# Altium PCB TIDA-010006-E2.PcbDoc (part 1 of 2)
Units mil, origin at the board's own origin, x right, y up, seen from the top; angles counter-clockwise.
Board outline 2251.83 x 2520.68 mil, 2 copper layers (Top Layer, Bottom Layer), stack 62 mil thick; 89 components, 37 nets, 190 pads, 37 vias.
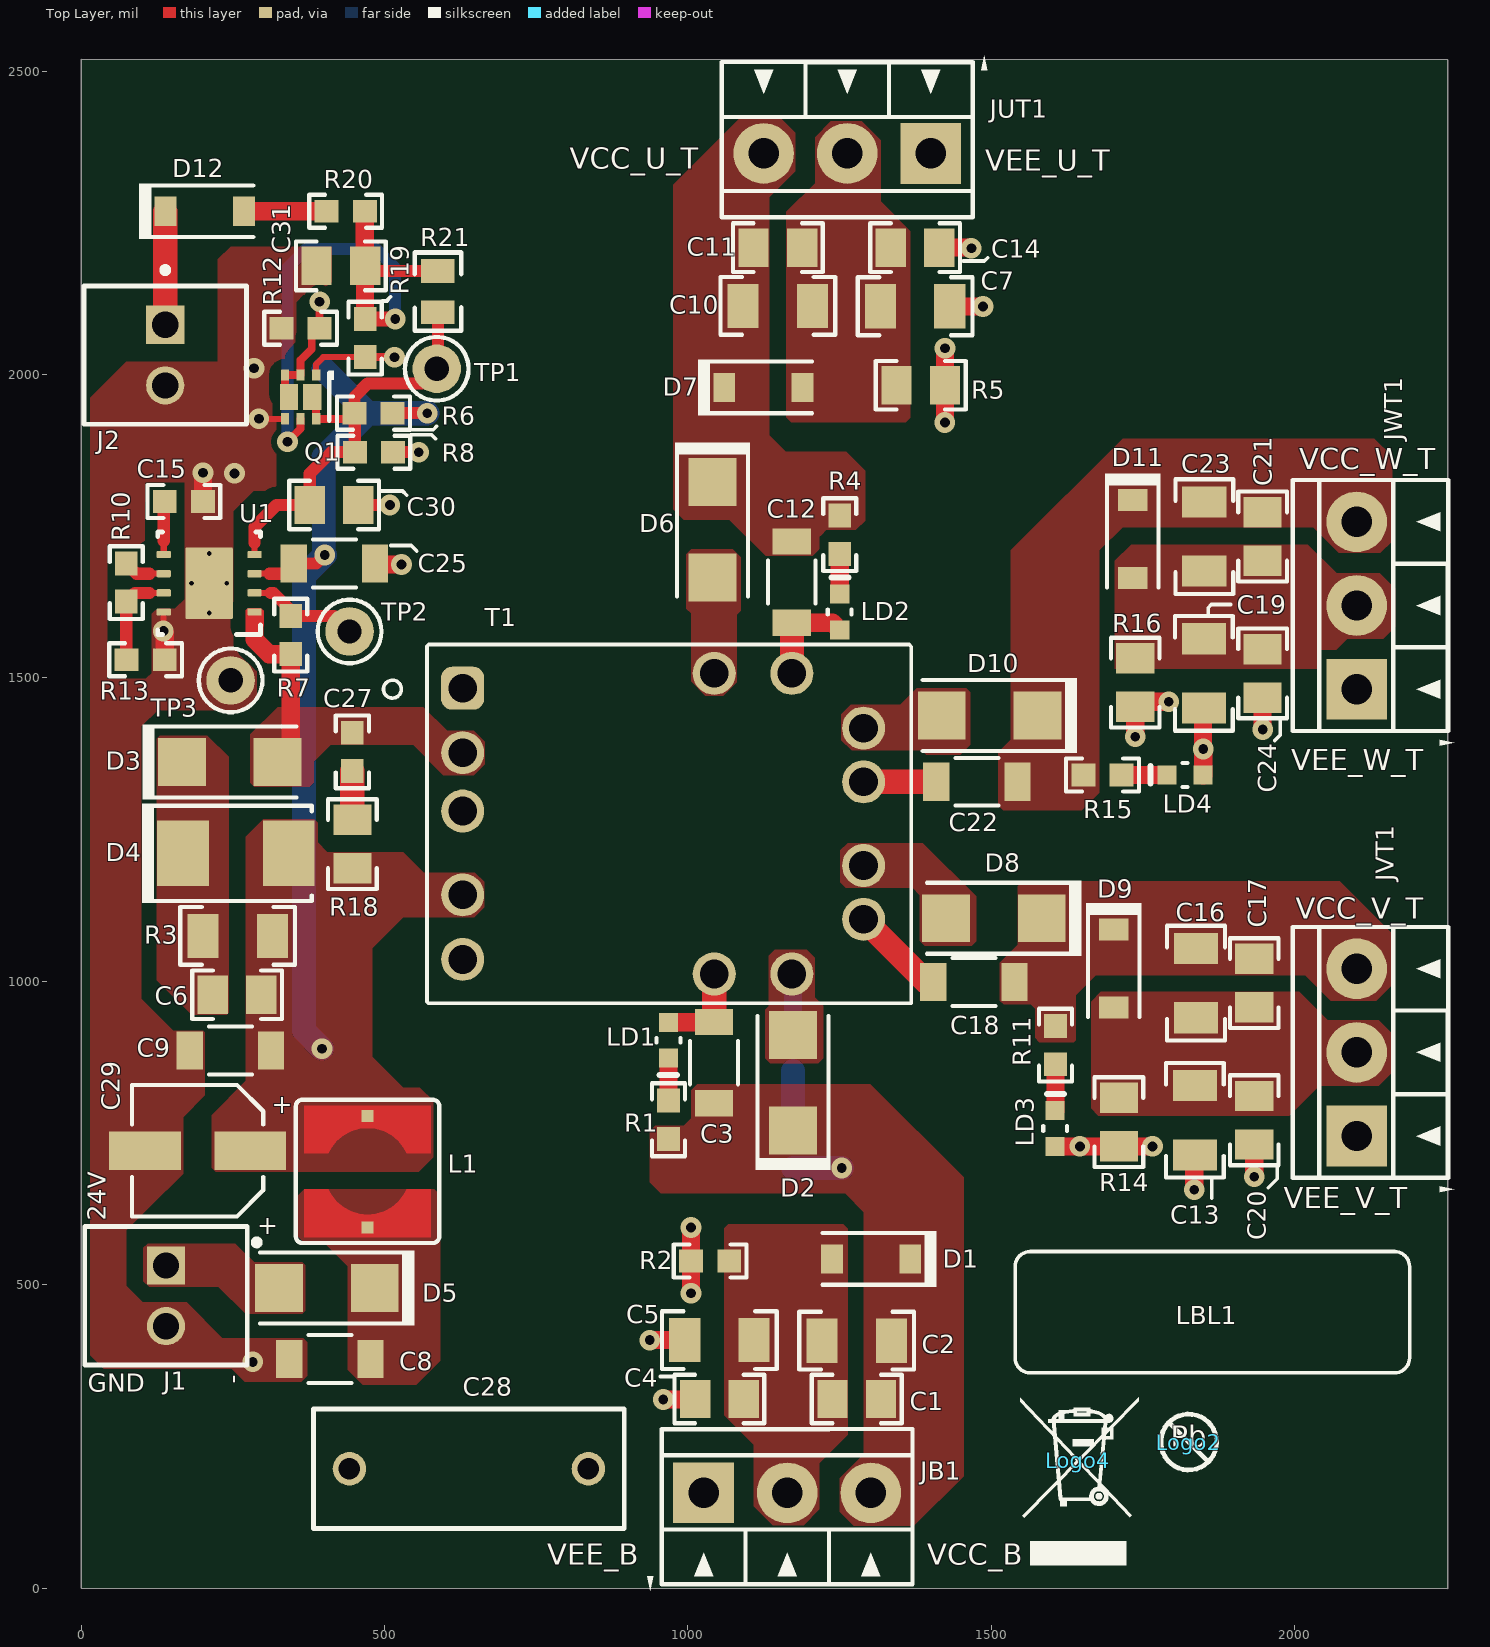
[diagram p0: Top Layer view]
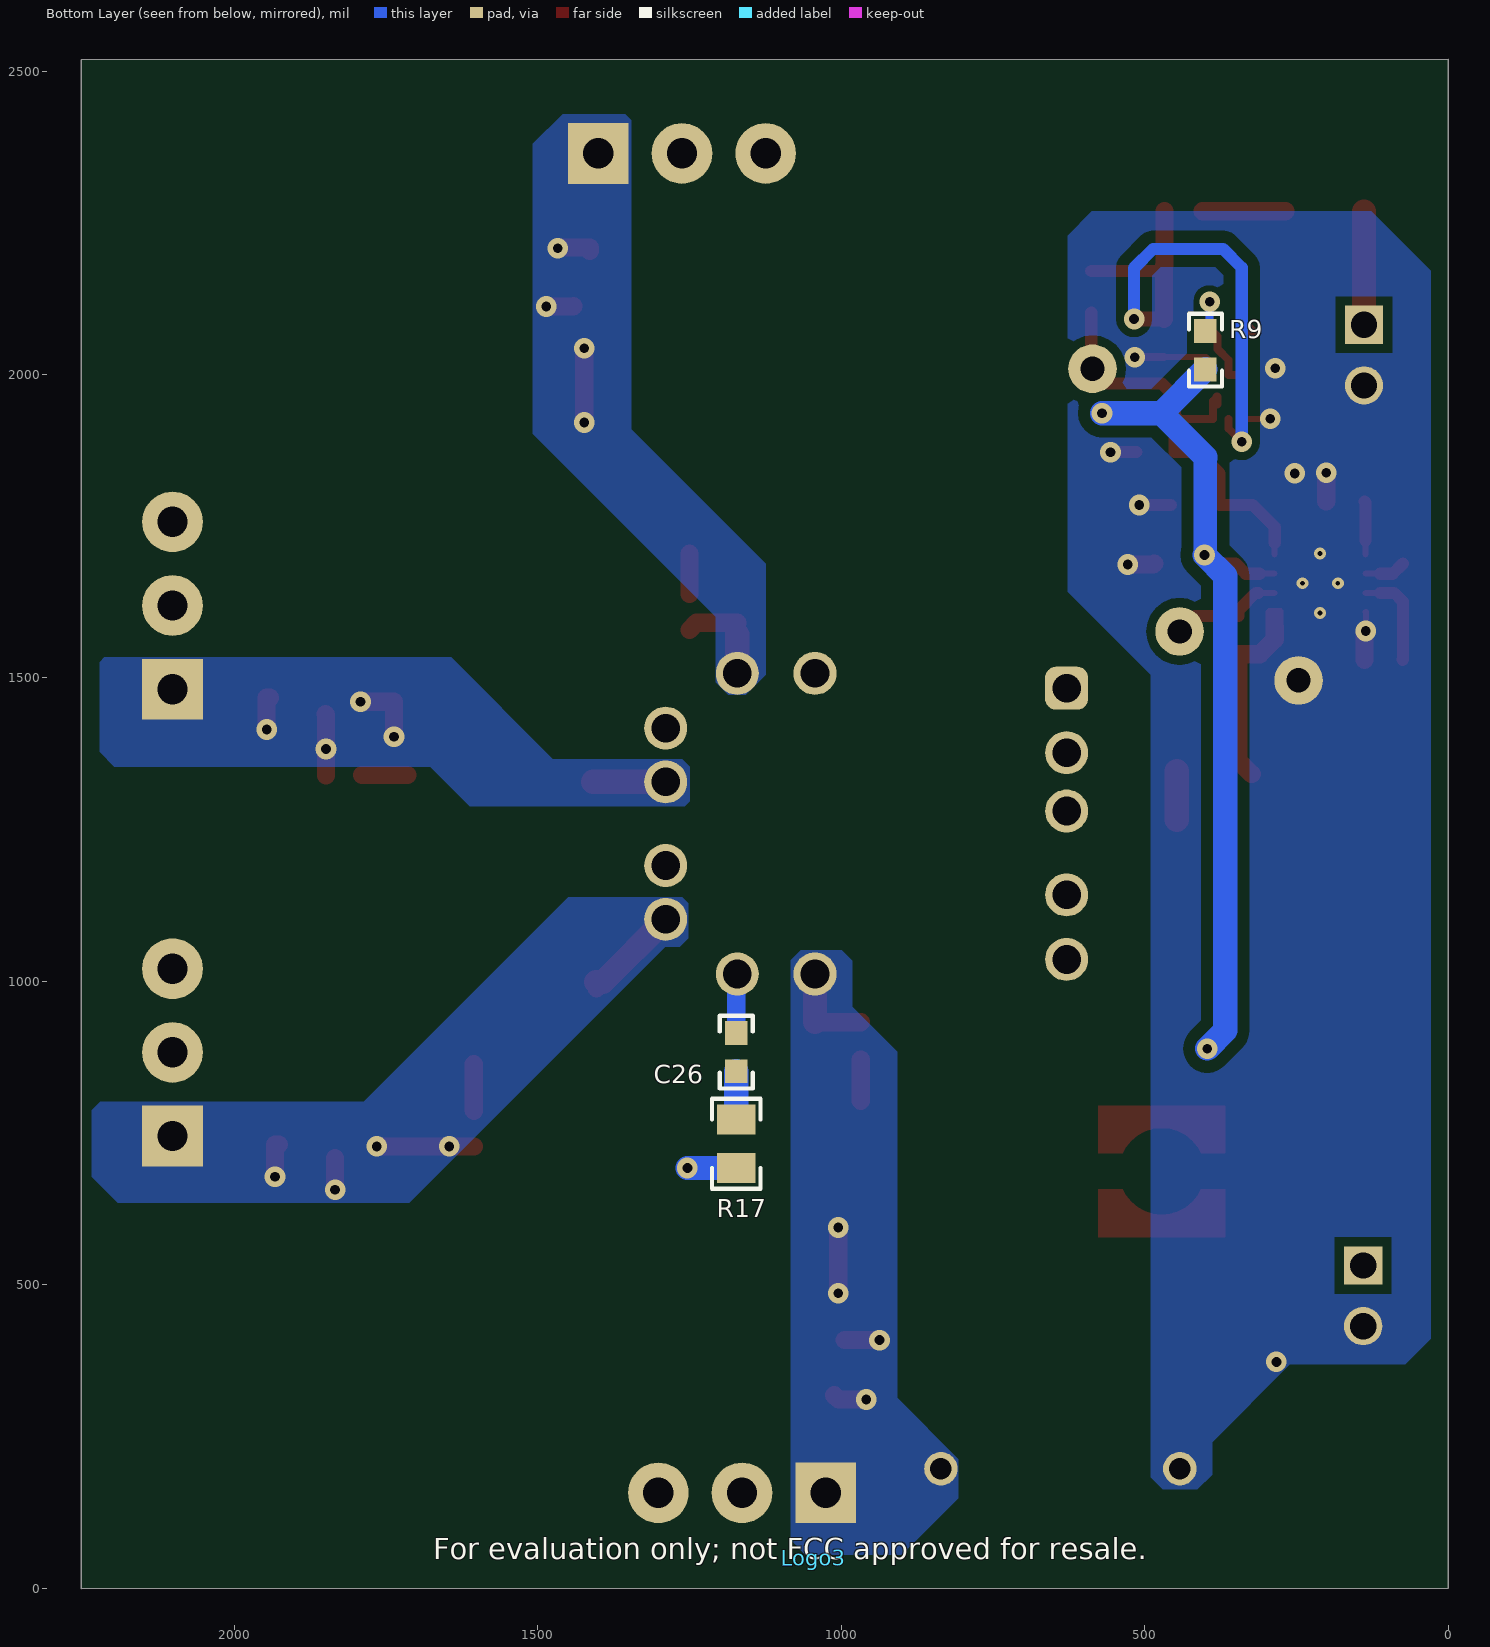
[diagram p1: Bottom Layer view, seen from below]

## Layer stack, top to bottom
Top Solder: solder mask 0.4, Solder Resist, Dk 3.5
Top Layer: signal copper 1.4
Dielectric1: core 59.2, FR-4 High Tg, Dk 4.8
Bottom Layer: signal copper 1.4
Bottom Solder: solder mask 0.4, Solder Resist, Dk 3.5

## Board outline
0,0 0,2519.68 2251.83,2518.68 2251.83,-1

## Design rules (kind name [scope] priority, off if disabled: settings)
AcuteAngle [All] p1: minimum=4.50000000000000E+0001 checktracksonly=FALSE
AssemblyTestPointUsage [All] p1: valid=2
BoardOutlineClearance BoardOutlineClearance_MountingHoles [OnCopper and InComponentClass('Mounting Holes')] p1: gap=20 ignorepadtopadclearanceinfootprint=FALSE
BoardOutlineClearance BoardOutlineClearance_Poly [OnCopper and IsPoly] p2: gap=15 ignorepadtopadclearanceinfootprint=FALSE
BoardOutlineClearance [OnCopper and Not InComponentClass('Logo') and not InComponentClass('FiducialMark') and not InRegion(1000,500,4000,800) and not InPoly] p3: gap=20 ignorepadtopadclearanceinfootprint=FALSE
Clearance Clearance_Keepouts [((IsTrack Or IsArc) And Not InPoly) And IsFree and IsKeepOut vs ((IsTrack Or IsArc) And Not InPoly) And IsFree and IsKeepOut] p1: gap=0 ignorepadtopadclearanceinfootprint=FALSE
Clearance Clearance_Poly [InPolygon] p2: gap=25 ignorepadtopadclearanceinfootprint=FALSE except(0: Arc-Hole Track-Hole SMDPad-Hole THPad-Hole Via-Hole Fill-Hole Poly-Hole Region-Hole Text-Hole; 10: Via-Fill Via-Poly Via-Region; 12: SMDPad-Fill SMDPad-Poly SMDPad-Region; 15: THPad-Fill THPad-Poly THPad-Region; 20: Arc-Fill Arc-Poly Arc-Region Track-Fill Track-Poly Track-Region)
Clearance Clearance_FiducialMark [IsKeepOut and InComponentClass('FiducialMark') vs IsPad and InComponentClass('FiducialMark')] p3: gap=0 ignorepadtopadclearanceinfootprint=FALSE
Clearance [All] p4: gap=7.87 ignorepadtopadclearanceinfootprint=TRUE except(0: Arc-Hole Track-Hole SMDPad-Hole THPad-Hole Via-Hole Fill-Hole Poly-Hole Region-Hole Text-Hole)
ComponentClearance ComponentClearance_MountingHoles_FiducialMarks [InComponentClass('Mounting Holes') vs InComponentClass('FiducialMark')] p1: gap=50 collisioncheckmode=3 verticalgap=10 showdistances=FALSE
ComponentClearance ComponentClearance_Shunt [InComponentClass('Header') vs InComponentClass('Shunt')] p2: gap=0 collisioncheckmode=3 verticalgap=0 showdistances=FALSE
ComponentClearance ComponentClearance_Logo [InComponentClass('Logo')] p3: gap=10 collisioncheckmode=3 verticalgap=10 showdistances=FALSE
ComponentClearance ComponentClearance_ScrewToNut [(HasFootprint('NY PMS 440 0025 PH')) vs (HasFootprint('Keystone_1902C'))] p4: gap=5 collisioncheckmode=3 verticalgap=10 showdistances=FALSE
ComponentClearance ComponentClearance_MountingHoles [InComponentClass('Mounting Holes')] p5: gap=15 collisioncheckmode=3 verticalgap=100000 showdistances=FALSE
ComponentClearance ComponentClearance_SmallPassives [HasFootprint('0201*') or HasFootprint('0402*') or HasFootprint('0508') or HasFootprint('0603*') or HasFootprint('0612') or HasFootprint('0805*') or HasFootprint('0815*') or HasFootprint('0830*') or HasFootprint('1206*') or HasFootprint('1210*') or HasFootprint('1808*') or HasFootprint('1812*') or HasFootprint('1825*') or HasFootprint('2010*') or HasFootprint('2220*') or HasFootprint('2225*') or HasFootprint('2512*') or HasFootprint('2728*') or HasFootprint('3518*') vs HasFootprint('0201*') or HasFootprint('0402*') or HasFootprint('0508') or HasFootprint('0603*') or HasFootprint('0612') or HasFootprint('0805*') or HasFootprint('0815*') or HasFootprint('0830*') or HasFootprint('1206*') or HasFootprint('1210*') or HasFootprint('1808*') or HasFootprint('1812*') or HasFootprint('1825*') or HasFootprint('2010*') or HasFootprint('2220*') or HasFootprint('2225*') or HasFootprint('2512*') or HasFootprint('2728*') or HasFootprint('3518*')] p6: gap=14.96 collisioncheckmode=3 verticalgap=10 showdistances=FALSE
ComponentClearance ComponentClearance_THtoSMT [IsThruComponent vs IsSMTComponent] p7: gap=15 collisioncheckmode=3 verticalgap=30 showdistances=FALSE
ComponentClearance ComponentClearance_THtoTH [IsThruComponent vs IsThruComponent] p8: gap=15 collisioncheckmode=3 verticalgap=30 showdistances=FALSE
ComponentClearance [All] p9: gap=15 collisioncheckmode=3 verticalgap=10 showdistances=FALSE
DiffPairsRouting [All] p1: maxlimit=100 minlimit=10 mostfreqgap=10 toplayer_minwidth=15 toplayer_maxwidth=15 toplayer_prefwidth=15 bottomlayer_minwidth=15 bottomlayer_maxwidth=15 bottomlayer_prefwidth=15 maxuncoupledlength=1000
FabricationTestPointUsage TestPointUsage [All] p1: valid=2 allowmultiple=FALSE
FabricationTestpoint Testpoint [All] p1: side=3 testpointundercomponent=TRUE minsize=40 maxsize=100 preferedsize=60 minholesize=0 maxholesize=40 preferedholesize=32 testpointgrid=1 allowsidetop=TRUE allowsidebottom=TRUE usegrid=TRUE gridtolerance=0.01
FanoutControl Fanout_LCC [IsLCC] p1: bgadir=Out bgaviamode=Centered fanoutstyle=Auto fanoutdirection=Alternating viagrid=1 // Fanout_LCC (Default Rule)
FanoutControl Fanout_BGA [IsBGA] p2: bgadir=Out bgaviamode=Centered fanoutstyle=Auto fanoutdirection=Alternating viagrid=1 // Fanout_BGA (Default Rule)
FanoutControl Fanout_Default [All] p4: bgadir=Out bgaviamode=Centered fanoutstyle=Auto fanoutdirection=Alternating viagrid=1 // Fanout_Default (Default Rule)
FanoutControl Fanout_Small [(CompPinCount < 5)] p5: bgadir=Out bgaviamode=Centered fanoutstyle=Auto fanoutdirection=OutThenIn viagrid=1 // Fanout_Small (Default Rule)
HoleSize [All] p1: absolutevalues=TRUE maxlimit=251 minlimit=7.87 maxpercent=80.000 minpercent=20.000
MinimumAnnularRing MinimumAnnularRing_ThermalPadVias [IsVia and InAnyComponent] p1: minimumring=5.91
MinimumAnnularRing [All] p2: minimumring=8
MinimumSolderMaskSliver MinimumSolderMaskSliver_Logo [InComponentClass('Logo') vs InComponentClass('Logo')] p1: minsoldermaskwidth=0.7
MinimumSolderMaskSliver [All] p2: minsoldermaskwidth=3.94
PlaneConnect [All] p1: planeconnectstyle=Relief reliefexpansion=10 reliefentries=4 reliefconductorwidth=10 reliefairgap=10
PolygonConnect [All] p1: connectstyle=Direct reliefconductorwidth=10 reliefentries=4 polygonreliefangle="90 Angle" airgapwidth=10
RoutingVias ThermalPadVias [IsVia and InAnyComponent] p1: holewidth=7.87 width=19.68 viastyle="Through Hole" minholewidth=7.87 minwidth=19.68 maxholewidth=12.99 maxwidth=23.62
RoutingVias [All] p2: holewidth=16 width=34 viastyle="Through Hole" minholewidth=7.87 minwidth=26 maxholewidth=40 maxwidth=65
SilkToBoardRegionClearance [Not ((IsComment or IsDesignator) And (Hide <> 'False')) and not InRegion(1000,500,4000,800)] p1:
SilkToSilkClearance SilkToSilkClearance_Pb-FreeLogo [(HasFootprint('Pb-Free_Overlay_Medium') OR HasFootprint('Pb-Free_Overlay_Small')) vs (HasFootprint('Pb-Free_Overlay_Medium') OR HasFootprint('Pb-Free_Overlay_Small'))] p1: silktosilkclearance=0
SilkToSilkClearance [All] p2: silktosilkclearance=4
SilkToSolderMaskClearance SilkToComponentPadClearance [(IsPad or IsFill or IsRegion) and InAnycomponent] p1: minsilkscreentomaskgap=5 clearancetoexposedcopper=TRUE
SilkToSolderMaskClearance "Silk to Solder Mask Opening" [All] p2: minsilkscreentomaskgap=4 clearancetoexposedcopper=FALSE
SolderMaskExpansion [All] p1: expansion=1.97
Width [All] p1: maxlimit=100 minlimit=6 preferedwidth=10 checkconnectedcopper=TRUE
15 further rules are at their usual default settings.

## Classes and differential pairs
component class Label: LBL1
component class AssemblyNote: ZZ1 ZZ2 ZZ3 ZZ4
component class TIDA010006_EVM_Hardware: LBL1 Logo2 Logo3 Logo4 ZZ1 ZZ2 ZZ3 ZZ4
component class TIDA010006Refresh_BlankSheet: C1 C2 C3 C4 C5 C6 C7 C8 C9 C10 C11 C12 C13 C14 C15 C16 C17 C18 C19 C20 C21 C22 C23 C24 C25 C26 C27 C28 C29 C30 C31 D1 D2 D3 D4 D5 D6 D7 D8 D9 D10 D11 D12 J1 J2 JB1 JUT1 JVT1 JWT1 L1 LD1 LD2 LD3 LD4 Q1 R1 R2 R3 R4 R5 R6 R7 R8 R9 R10 R11 R12 R13 R14 R15 R16 R17 R18 R19 R20 R21 T1 TP1 TP2 TP3 U1

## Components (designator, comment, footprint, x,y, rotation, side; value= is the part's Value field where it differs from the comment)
C1 "UMK212B7104KG-T" 0805_HV 1278,312 r180 top value=0.1uF
C2 "GMK316AB7106KL" 1206 1278,408 r180 top value=10uF
C3 "C3216X7R1H475K160AC" 1206_180 1043,866 r90 top value=4.7uF
C4 "UMK212B7104KG-T" 0805_HV 1051.7,312 r180 top value=0.1uF
C5 "EMK316BB7226ML-T" 1206 1051.7,409.06 r180 top value=22uF
C6 "C0805C124K1RACTU" 0805_HV 257,978 r0 top value=0.12uF
C7 "EMK316BB7226ML-T" 1206 1374.22,2112.46 r0 top value=22uF
C8 "C3216X7R1H475K160AC" 1206_180 410,378 r180 top value=4.7uF
C9 "C3216X7R1H475K160AC" 1206_180 246,886 r180 top value=4.7uF
C10 "GMK316AB7106KL" 1206 1148,2113 r0 top value=10uF
C11 "UMK212B7104KG-T" 0805_HV 1148,2209 r0 top value=0.1uF
C12 "C3216X7R1H475K160AC" 1206_180 1171,1658 r270 top value=4.7uF
C13 "EMK316BB7226ML-T" 1206 1835.2,771.2 r270 top value=22uF
C14 "UMK212B7104KG-T" 0805_HV 1374.22,2209 r0 top value=0.1uF
C15 "GRM188R71H392KA01D" 0603 169.43,1790.63 r0 top value=3900pF
C16 "GMK316AB7106KL" 1206 1837,997.17 r270 top value=10uF
C17 "UMK212B7104KG-T" 0805_HV 1933,997.17 r270 top value=0.1uF
C18 "C3216X7R1H475K160AC" 1206_180 1471,999 r180 top value=4.7uF
C19 "EMK316BB7226ML-T" 1206 1850,1507.53 r270 top value=22uF
C20 "UMK212B7104KG-T" 0805_HV 1933,771.2 r270 top value=0.1uF
C21 "UMK212B7104KG-T" 0805_HV 1946.8,1733 r270 top value=0.1uF
C22 "C3216X7R1H475K160AC" 1206_180 1476,1329 r180 top value=4.7uF
C23 "GMK316AB7106KL" 1206 1850.8,1733 r270 top value=10uF
C24 "UMK212B7104KG-T" 0805_HV 1946.8,1507.53 r270 top value=0.1uF
C25 "C3216X7R1H475K160AC" 1206_180 417.43,1688.63 r0 top value=4.7uF
C26 "GRM188R72A221KA01D" 0603 1173,883.5 r270 bottom value=220pF
C27 "GRM188R72A221KA01D" 0603 447,1378.26 r270 top value=220pF
C28 "890334023006" WCAP-FTXX_P10PL20_13x5x11 639,197 r180 top value=0.01uF
C29 "EMVA500ADA100ME55G" CAPSMT_62_E55 192,721 r180 top value=10uF
C30 "0805YC334KAT2A" 0805_HV 416.83,1785 r0 top value=0.33uF
C31 "UMK212B7104KG-T" 0805_HV 428,2179 r180 top value=0.1uF
D1 "MMSZ4702T1G" SOD-123 1301.7,542.74 r180 top value=15V
D2 "B2100A-13-F" SMA 1173,833 r90 top value=100V
D3 "B2100A-13-F" SMA 245,1361.63 r0 top value=100V
D4 "1SMB5942BT3G" SMB 255,1211 r0 top value=51V
D5 "B2100A-13-F" SMA 405,495 r180 top value=100V
D6 "B2100A-13-F" SMA 1040.43,1744.26 r270 top value=100V
D7 "MMSZ4702T1G" SOD-123 1124.22,1978.78 r0 top value=15V
D8 "B2100A-13-F" SMA 1504,1104 r180 top value=100V
D9 "MMSZ4702T1G" SOD-123 1701.52,1021.2 r270 top value=15V
D10 "B2100A-13-F" SMA 1497,1438 r180 top value=100V
D11 "MMSZ4702T1G" SOD-123 1732.8,1729 r270 top value=15V
D12 "MMSZ5248B-7-F" SOD-123 203.73,2269 r0 top value=18V
J1 "282834-2" TEC_282834-2 140,482 r270 top
J2 "282834-2" TEC_282834-2 138.63,2032 r270 top
JB1 "ED555/3DS" TERM_BLK_ED555-3DS 1025.7,157.26 r0 top
JUT1 "ED555/3DS" TERM_BLK_ED555-3DS 1400.22,2364.26 r180 top
JVT1 "ED555/3DS" TERM_BLK_ED555-3DS 2101.8,745.2 r90 top
JWT1 "ED555/3DS" TERM_BLK_ED555-3DS 2101.8,1481.53 r90 top
L1 "744042100" WE-TPC-M1 472,687 r90 top value=10uH
LBL1 "THT-14-423-10" Label_650x200 1864,455 r0 top
LD1 "LED_LG L29K-G2J1-24-Z" "LG L29K_GREEN" 968,903 r270 top value=Green
LD2 "LED_LG L29K-G2J1-24-Z" "LG L29K_GREEN" 1250,1608.76 r90 top value=Green
LD3 "LED_LG L29K-G2J1-24-Z" "LG L29K_GREEN" 1605,757.5 r90 top value=Green
LD4 "LED_LG L29K-G2J1-24-Z" "LG L29K_GREEN" 1819,1340 r180 top value=Green
Logo2 "Pb-Free Symbol" Pb-Free_Overlay_Small 1825,241 r0 top
Logo3 "FCC disclaimer" FCC_disclaimer 1045,50 r180 bottom
Logo4 "WEEE logo" WEEE_Minimum 1643,210 r0 top
Q1 "NSS60101DMTTBG" DFN2x2MM_6L 361.63,1963 r270 top value="60 V"
R1 "RC0603FR-0718KL" 0603 968,772 r270 top value=18.0k
R2 "RC0603FR-079K1L" 0603 1036.43,539.26 r0 top value=9.10k
R3 "ERJ-8ENF3481V" 1206 258,1075 r180 top value=3.48k
R4 "RC0603FR-0718KL" 0603 1250,1736 r90 top value=18.0k
R5 "RC0805FR-07649RL" 0805_HV 1383.49,1982.26 r180 top value=649
R6 "RT0603BRD07261KL" 0603 481.83,1936.28 r0 top value=261k
R7 "RC0603FR-07210KL" 0603 345.43,1570.63 r270 top value=210k
R8 "RC0603FR-0720KL" 0603 482.5,1872 r180 top value=20.0k
R9 "RT0603BRD07261KL" 0603 400,2040 r270 bottom value=261k
R10 "RC0603FR-07665KL" 0603 74.43,1657.17 r90 top value=665k
R11 "RC0603FR-0718KL" 0603 1605.46,895 r90 top value=18.0k
R12 "RC0603FR-0720KL" 0603 361.63,2076 r0 top value=20.0k
R13 "RT0603DRE0712K1L" 0603 106.43,1530 r180 top value=12.1k
R14 "RC0805FR-07649RL" 0805_HV 1710,768.11 r90 top value=649
R15 "RC0603FR-0718KL" 0603 1683,1340 r180 top value=18.0k
R16 "RC0805FR-07649RL" 0805_HV 1736.8,1492.26 r90 top value=649
R17 "RG2012P-101-B-T5" 0805_HV 1173,732.5 r90 bottom value=100
R18 "RG2012P-101-B-T5" 0805_HV 447,1226.26 r90 top value=100
R19 "RC0603FR-0720KL" 0603 468,2060 r270 top value=20.0k
R20 "RG1608P-2211-B-T5" 0603 436,2269 r180 top value=2.21k
R21 "5106" 5106 588,2137 r270 top value=0
T1 "750343953" Wurth_EPW15_5996 959,1259.84 r0 top locked value=47uH
TP1 "5000" Keystone5000 586,2009.46 r90 top
TP2 "5000" Keystone5000 442.43,1576.63 r90 top
TP3 "5001" Keystone5001 246.43,1496 r90 top
U1 "LM5180QNGURQ1" NGU0008C 211,1656 r180 top
ZZ1 "This Assembly Note is for PCB labels only" AssemblyNoteLabel -943.43,3340.63 r0 top
ZZ2 "These assemblies are ESD sensitive, ESD precautions shall be observed." AssemblyNote -943.43,3231.74 r0 top
ZZ3 "These assemblies must be clean and free from flux and all contaminants. Use of no clean flux is not acceptable." AssemblyNote -943.43,3143.19 r0 top
ZZ4 "These assemblies must comply with workmanship standards IPC-A-610 Class 2, unless otherwise specified." AssemblyNote -943.43,3054.63 r0 top

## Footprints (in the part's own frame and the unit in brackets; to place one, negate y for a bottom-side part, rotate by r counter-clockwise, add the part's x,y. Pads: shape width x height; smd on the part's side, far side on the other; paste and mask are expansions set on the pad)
0603 [mm] "0603 from SM-752 data"
  rect 1x0.95 smd: 1(-0.8,0) 2(0.8,0)
  silkscreen extent -1.52,-0.69 1.52,0.69, body extent -0.87,-0.47 0.87,0.47, height 1
0805_HV [mil] "0805 with 30mil clearance between pads"
  rect 50x63 smd: 1(-40,0) 2(40,0)
  silkscreen extent -74,-40 74,40, body extent -43,-29 43,29, height 57
1206 [mm] "1206 from SM-752 data"
  rect 1.3x1.85 smd: 1(-1.45,0) 2(1.45,0)
  silkscreen extent -2.4,-1.21 2.4,1.21, body extent -1.7,-0.9 1.7,0.9, height 1.35
1206_180 [mm] "1206_180"
  rect 1.1x1.6 smd: 1(-1.7,0) 2(1.7,0)
  silkscreen extent -0.9,-1 0.9,1, body extent -1.75,-0.95 1.75,0.95, height 1.8
5106 [mm] "Keystone"
  rect 0.99x1.4 smd: 1(-0.85,0) 2(0.88,0)
  silkscreen extent -1.63,-0.97 1.65,0.98, body extent -1.06,-0.69 1.06,0.69, height 0.84
AssemblyNote [mil] "Assembly Note"
AssemblyNoteLabel [mil] "Assembly Note for PCB Labels"
CAPSMT_62_E55 [mm] "5 x 5.2mm:  Chemi-Con E55"
  rect 3x1.6 smd: 1(-2.2,0) 2(2.2,0)
  silkscreen extent -2.75,-2.75 2.75,2.75, body extent -2.75,-2.75 2.75,2.75, height 5.5
DFN2x2MM_6L [mm] "SMD, 6-Leads, Body 2x2mm, Pitch 0.65mm"
  rect 0.47x0.35 smd: 1(-0.915,0.65) 2(-0.915,0) 3(-0.915,-0.65) 4(0.915,-0.65) 5(0.915,0) 6(0.915,0.65)
  rect 1.1x0.77 smd: 7(0,0.485) 8(0,-0.485)
  silkscreen extent -1.1,1.2 1,1.4, body extent -1,-1 1,1, height 0.81
FCC_disclaimer [mil]
Keystone5000 [mil] "For Keystone 500x miniature loop terminals"
  round 80 hole 40: 1(0,0)
  silkscreen extent -52,-52 52,52, body extent -49,-49 49,49, height 182
Keystone5001 [mil] "For Keystone 500x miniature loop terminals"
  round 80 hole 40: 1(0,0)
  silkscreen extent -52,-52 52,52, body extent -49,-49 49,49, height 182
Label_650x200 [mil] "Thermal Transfer Label"
  round 1 on Mech13: 0(0,0)
  silkscreen extent -325,-100 325,100, body extent -325,-100 325,100, height 1
"LG L29K_GREEN" [mm] "OSRAM"
  rect 0.8x0.8 smd paste-0.4: 1(-0.75,0) 2(0.75,0)
  silkscreen extent -0.1,-0.5 1.45,0.5, body extent -0.9,-0.45 0.9,0.45, height 0.67
NGU0008C [mm] "SON, 8-Leads, Body 4x4mm, Pitch 0.8mm"
  rrect33% 0.6x0.3 smd: 1(-1.9,1.2) 2(-1.9,0.4) 3(-1.9,-0.4) 4(-1.9,-1.2) 5(1.9,-1.2) 6(1.9,-0.4) 7(1.9,0.4) 8(1.9,1.2)
  rrect8% 1.75x1.31 on Top Paste: 9(0,0.755) 9(0,-0.755)
  rrect5% 1.98x3 smd paste-1.5: 9(0,0)
  silkscreen extent -2.15,-2.15 2.15,2.15, body extent -2,-2 2,2, height 0.77
Pb-Free_Overlay_Small [mil]
  silkscreen extent -46,-46 46,46
SMA [mm] "Molded Diode, 2-Leads, Body 4.3x2.6mm, IPC Medium Density, based on OnSemi component dimensions and land pattern"
  rect 2x2 smd: 1(-2,0) 2(2,0)
  silkscreen extent -3.66,-1.57 2.79,1.57, body extent -2.6,-1.3 2.6,1.3, height 2.42
SMB [mil] "Molded Diode, 2-Leads, Body 5.4x3.6mm, IPC Medium Density, based on OnSemi component dimensions"
  rect 85x107.99 smd: 1(-87.01,0) 2(87.01,0)
  silkscreen extent -155,-82 125,82, body extent -106,-71 106,71, height 91
SOD-123 [mm] "On Semi recommended land pattern"
  rect 0.915x1.22 smd: 1(-1.637,0) 2(1.637,0)
  silkscreen extent -2.74,-1.17 2.03,1.17, body extent -1.93,-0.9 1.93,0.9, height 1.35
TEC_282834-2 [mm] "TEC"
  rect 1.6x1.6 hole 1.1: 1(-1.27,0)
  round 1.6 hole 1.1: 2(1.27,0)
  silkscreen extent -2.9,-3.4 2.9,3.9, body extent -2.77,-3.25 2.77,3.25, height 10.01
TERM_BLK_ED555-3DS [mm]
  rect 2.54x2.54 hole 1.27: 1(0,0)
  round 2.54 hole 1.27: 2(3.5,0) 3(7,0)
  silkscreen extent -2.36,-4.09 8.75,2.67, body extent -1.75,-3.83 8.75,2.67, height 8.2
WCAP-FTXX_P10PL20_13x5x11 [mm] "TH, 2-Leads, Body 13x5mm, Pitch 10mm"
  round 1.4 hole 0.9: 1(-5,0) 2(5,0)
  silkscreen extent -6.5,-2.5 6.5,2.5, body extent -6.5,-2.5 6.5,2.5, height 11
WE-TPC-M1 [mm] "Wurth Elektronik recommended land pattern"
  rect 0.5x0.5 smd: 1(-2.35,0) 2(2.325,0)
  Top Layer region: -0.75,1.64 -1.005,1.504 -1.279,1.279 -1.504,1.005 -1.671,0.692 -1.774,0.353 -1.809,0 -1.774,-0.353 -1.671,-0.692 -1.504,-1.005 -1.279,-1.279 -1.005,-1.504 -0.75,-1.64 -0.75,-2.65 -2.75,-2.65 -2.75,2.65 -0.75,2.65
  Top Layer region: 0.75,1.64 1.005,1.504 1.279,1.279 1.504,1.005 1.671,0.692 1.774,0.353 1.809,0 1.774,-0.353 1.671,-0.692 1.504,-1.005 1.279,-1.279 1.005,-1.504 0.75,-1.64 0.75,-2.65 2.75,-2.65 2.75,2.65 0.75,2.65
  silkscreen extent -3,-3 3,3, body extent -2.5,-2.5 2.5,2.5, height 2
WEEE_Minimum [mil] "WEEElie bin"
  silkscreen extent -95,-172 99,104
Wurth_EPW15_5996 [mm] "TH, 13-Leads, Body 22.1x15.7mm"
  rrect50% 1.8x1.8 hole 1.2: 1(-8.39,5.67)
  round 1.8 hole 1.2: 2(-8.39,2.97) 3(-8.39,0.53) 4(-8.39,-2.98) 5(-8.39,-5.68) 6(2.14,-6.29) 7(2.14,6.29) 8(5.39,6.29) 11(5.39,-6.29) 12(8.39,-4) 13(8.39,-1.75) 14(8.39,1.75) 15(8.39,4)
  body extent -10.9,-7.5 10.4,7.52, height 22.6

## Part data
C1 C4 C11 C14 C17 C20 C21 C24 C31: library part CMP-0008420-2, "CAP, CERM, 0.1 uF, 50 V, +/- 10%, X7R, 0805", Cap_Case=0805, Manufacturer="Taiyo Yuden", Supplier Part Number 1=587-1279-1-ND, TempCo=X7R, Tolerance_%=10%, Value1=Unknown, Value2=50V, ValueDisplayed=0.1uF
C2 C10 C16 C23: library part CMP-0008821-2, "CAP, CERM, 10 uF, 35 V, +/- 10%, X7R, 1206", Cap_Case=1206, Manufacturer="Taiyo Yuden", Supplier Part Number 1=587-3007-1-ND, TempCo=X7R, Tolerance_%=10%, Value1=Unknown, Value2=35V, ValueDisplayed=10uF
C3 C8 C9 C12 C18 C22 C25: library part CMP-0008702-2, "CAP, CERM, 4.7 uF, 50 V, +/- 10%, X7R, 1206", Cap_Case=1206_180, Manufacturer=TDK, Supplier Part Number 1=445-8032-1-ND, TempCo=X7R, Tolerance_%=10%, Value1="0.003158 ohm", Value2=50V, ValueDisplayed=4.7uF
C5 C7 C13 C19: library part CMP-0008805-2, "CAP, CERM, 22 uF, 16 V, +/- 20%, X7R, 1206_190", Cap_Case=1206, Manufacturer="Taiyo Yuden", Supplier Part Number 1=587-4319-1-ND, TempCo=X7R, Tolerance_%=20%, Value1=Unknown, Value2=16V, ValueDisplayed=22uF
C6: library part CMP-0007738-2, "CAP, CERM, 0.12 uF, 100 V, +/- 10%, X7R, 0805", Cap_Case=0805, Manufacturer=Kemet, Supplier Part Number 1=399-3488-1-ND, TempCo=X7R, Tolerance_%=10%, Value1="0.059 ohm", Value2=100V, ValueDisplayed=0.12uF
C15: library part CMP-0007453-4, "CAP, CERM, 3900 pF, 50 V, +/- 10%, X7R, 0603", Cap_Case=0603, Manufacturer=MuRata, Supplier Part Number 1=490-1504-1-ND, TempCo=X7R, Tolerance_%=10%, Value1=Unknown, Value2=50V, ValueDisplayed=3900pF
C26 C27: library part CMP-0007474-4, "CAP, CERM, 220 pF, 100 V, +/- 10%, X7R, 0603", Cap_Case=0603, Manufacturer=MuRata, Supplier Part Number 1=490-1460-1-ND, TempCo=X7R, Tolerance_%=10%, Value1=Unknown, Value2=100V, ValueDisplayed=220pF
C28: library part CMP-0012317-3, "CAP, Film, 0.01 uF, 310 V, +/- 10%, TH", Cap_Case=13x5x11mm, Manufacturer="Wurth Elektronik", Supplier Part Number 1=732-5824-ND, Tolerance_%=10%, Value1=Unknown, Value2=310V, ValueDisplayed=0.01uF
C29: library part CMP-0011235-3, "CAP, AL, 10 uF, 50 V, +/- 20%, SMD", Cap_Case=E55, Manufacturer=Chemi-Con, Supplier Part Number 1=565-2129-1-ND, Tolerance_%=20%, Value1=Unknown, Value2=50V, ValueDisplayed=10uF
C30: library part CMP-0007673-2, "CAP, CERM, 0.33 uF, 16 V, +/- 10%, X7R, 0805", Cap_Case=0805, Manufacturer=AVX, Supplier Part Number 1=478-1402-1-ND, TempCo=X7R, Tolerance_%=10%, Value1="0.013 ohm", Value2=16V, ValueDisplayed=0.33uF
D1 D7 D9 D11: library part CMP-0005745-2, "Diode, Zener, 15 V, 500 mW, SOD-123", Manufacturer="ON Semiconductor", Power_W=500mW, Supplier Part Number 1=MMSZ4702T1GOSCT-ND, Value1=0.5W
D2 D3 D5 D6 D8 D10: library part CMP-0081099-1, "Diode, Schottky, 100 V, 2 A, SMA", Manufacturer="Diodes Inc.", Supplier Part Number 1=B2100A-13-FDICT-ND, Value1=2A, Value2=0.79V
D4: library part CMP-0005610-2, "Diode, Zener, 51 V, 550 mW, SMB", Manufacturer="ON Semiconductor", Power_W=550mW, Supplier Part Number 1=71J9221, Value1=0.55W
D12: library part CMP-0005755-4, "Diode, Zener, 18 V, 500 mW, SOD-123", Manufacturer="Diodes Inc.", Power_W=500mW, Value1=0.5W
J1 J2: library part CMP-0054974-1, "Terminal Block, 2x1, 2.54mm, TH", Manufacturer="TE Connectivity", Supplier Part Number 1=A98333-ND
JB1 JUT1 JVT1 JWT1: "Terminal Block, 6A, 3.5mm Pitch, 3-Pos, TH", Manufacturer="On-Shore Technology", Supplier Part Number 1=ED1515-ND
L1: library part CMP-0063804-1, "Inductor, Shielded Drum Core, Ferrite, 10 uH, 1 A, 0.12 ohm, SMD", Manufacturer="Wurth Elektronik", Supplier Part Number 1=732-1025-1-ND, Value1="0.12 ohm", Value2=1A, ValueDisplayed=10uH
LBL1: library part CMP-0003625-1, "Thermal Transfer Printable Labels, 0.650\" W x 0.200\" H - 10,000 per roll", Manufacturer=Brady, Supplier Part Number 1=97C5133
LD1 LD2 LD3 LD4: "LED SmartLED Green 570NM", Alternate Manufacturer=LED, Manufacturer=OSRAM, PartNumber="LG L29K-G2J1-24-Z", Supplier Part Number 1=475-2709-2-ND
Logo2: library part CMP-0074839-1
Logo3: library part CMP-0074847-1, "FCC_disclaimer"
Logo4: library part CMP-0074769-1
Q1: library part CMP-0000492-2, "Transistor, Dual NPN, 60 V, 1 A, AEC-Q101, 6-WDFN", Manufacturer="ON Semiconductor", Supplier Part Number 1=NSS60101DMTTBG-ND, Value1="1 A"
R1 R4 R11 R15: library part CMP-0022852-5, "RES, 18.0 k, 1%, 0.1 W, 0603", Manufacturer=Yageo, Power_W=100mW, Supplier Part Number 1=311-18.0KHRCT-ND, TempCo="100 ppm/C", Tolerance_%=1%, Value2=0.1W, Value_Code=18k0, ValueDisplayed=18.0k
R2: library part CMP-0023333-5, "RES, 9.10 k, 1%, 0.1 W, 0603", Manufacturer=Yageo, Power_W=100mW, Supplier Part Number 1=311-9.10KHRCT-ND, TempCo="100 ppm/C", Tolerance_%=1%, Value2=0.1W, Value_Code=9k10, ValueDisplayed=9.10k
R3: library part CMP-0017552-2, "RES, 3.48 k, 1%, 0.25 W, 1206", Manufacturer=Panasonic, Power_W=250mW, Supplier Part Number 1=P3.48KFCT-ND, TempCo="100 ppm/C", Tolerance_%=1%, Value2=0.25W, Value_Code=3k48, ValueDisplayed=3.48k
R5 R14 R16: library part CMP-0082503-1, "RES, 649, 1%, 0.125 W, 0805", Manufacturer=Yageo, Power_W=125mW, Supplier Part Number 1=311-649CRCT-ND, TempCo="100 ppm/C", Tolerance_%=1%, Value2=0.125W, Value_Code=649R, ValueDisplayed=649
R6 R9: library part CMP-0024008-3, "RES, 261 k, 0.1%, 0.1 W, 0603", Manufacturer="Yageo America", Power_W=100mW, TempCo="25 ppm/C", Tolerance_%=0.1%, Value2=0.1W, Value_Code=261k
R7: library part CMP-0022909-4, "RES, 210 k, 1%, 0.1 W, 0603", Manufacturer=Yageo, Power_W=100mW, Supplier Part Number 1=311-210KHRCT-ND, TempCo="100 ppm/C", Tolerance_%=1%, Value2=0.1W, Value_Code=210k
R8 R12 R19: library part CMP-0022906-3, "RES, 20.0 k, 1%, 0.1 W, 0603", Manufacturer="Yageo America", Power_W=100mW, Supplier Part Number 1=311-20.0KHRCT-ND, TempCo="200 ppm/C", Tolerance_%=1%, Value2=0.1W, Value_Code=20k0, ValueDisplayed=20.0k
R10: library part CMP-0023230-4, "RES, 665 k, 1%, 0.1 W, 0603", Manufacturer=Yageo, Power_W=100mW, Supplier Part Number 1=311-665KHRCT-ND, TempCo="100 ppm/C", Tolerance_%=1%, Value2=0.1W, Value_Code=665k
R13: library part CMP-0024637-3, "RES, 12.1 k, 0.5%, 0.1 W, 0603", Manufacturer="Yageo America", Power_W=100mW, TempCo="50 ppm/C", Tolerance_%=0.5%, Value2=0.1W, Value_Code=12k1, ValueDisplayed=12.1k
R17 R18: library part CMP-0018851-2, "RES, 100, 0.1%, 0.125 W, 0805", Manufacturer="Susumu Co Ltd", Power_W=125mW, Supplier Part Number 1=RG20P100BCT-ND, TempCo="25 ppm/C", Tolerance_%=0.1%, Value2=0.125W, Value_Code=100R, ValueDisplayed=100
R20: library part CMP-0023469-3, "RES, 2.21 k, 0.1%, 0.1 W, 0603", Manufacturer="Susumu Co Ltd", Power_W=100mW, Supplier Part Number 1=RG16P2.21KBCT-ND, TempCo="25 ppm/C", Tolerance_%=0.1%, Value2=0.1W, Value_Code=2k21, ValueDisplayed=2.21k
R21: library part CMP-0020833-2, "RES, 0, 1%, 0.5 W, 0805", Manufacturer=Keystone, Power_W=500mW, Supplier Part Number 1=36-5106CT-ND, TempCo=ppm/C, Tolerance_%=1%, Value2=0.5W, Value_Code=0
T1: library part CMP-0082101-1, "Transformer, 47 uH, TH", Manufacturer="Wurth Elektronik", ValueDisplayed=47µH
TP1 TP2: library part CMP-0055137-1, "Test Point, Miniature, Red, TH", Color=Red, Manufacturer=Keystone, Supplier Part Number 1=36-5000-ND
TP3: library part CMP-0055138-1, "Test Point, Miniature, Black, TH", Color=Black, Manufacturer=Keystone, Supplier Part Number 1=36-5001-ND
U1: library part CMP-0078633-2, "70-V PSR Flyback Converter With 100-V, 1.2-A Power Switch and Ultra-Low IQ, NGU0008C (WSON-8)", Alternate Manufacturer="Texas Instruments", Alternate PartNumber=LM5180QNGUTQ1
ZZ1: library part CMP-0003616-3
ZZ2: library part CMP-0077236-1
ZZ3: library part CMP-0077237-1
ZZ4: library part CMP-0077238-1

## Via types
v1: diameter 34, hole 16, Top Layer to Bottom Layer, 33 vias
v2: diameter 19.68, hole 7.87, Top Layer to Bottom Layer, 4 vias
